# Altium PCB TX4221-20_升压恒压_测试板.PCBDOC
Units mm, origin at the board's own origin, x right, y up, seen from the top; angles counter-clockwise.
Board outline 40.25 x 32.29 mm, 2 copper layers (TopLayer, BottomLayer); 23 components, 11 nets, 61 pads, 124 vias.
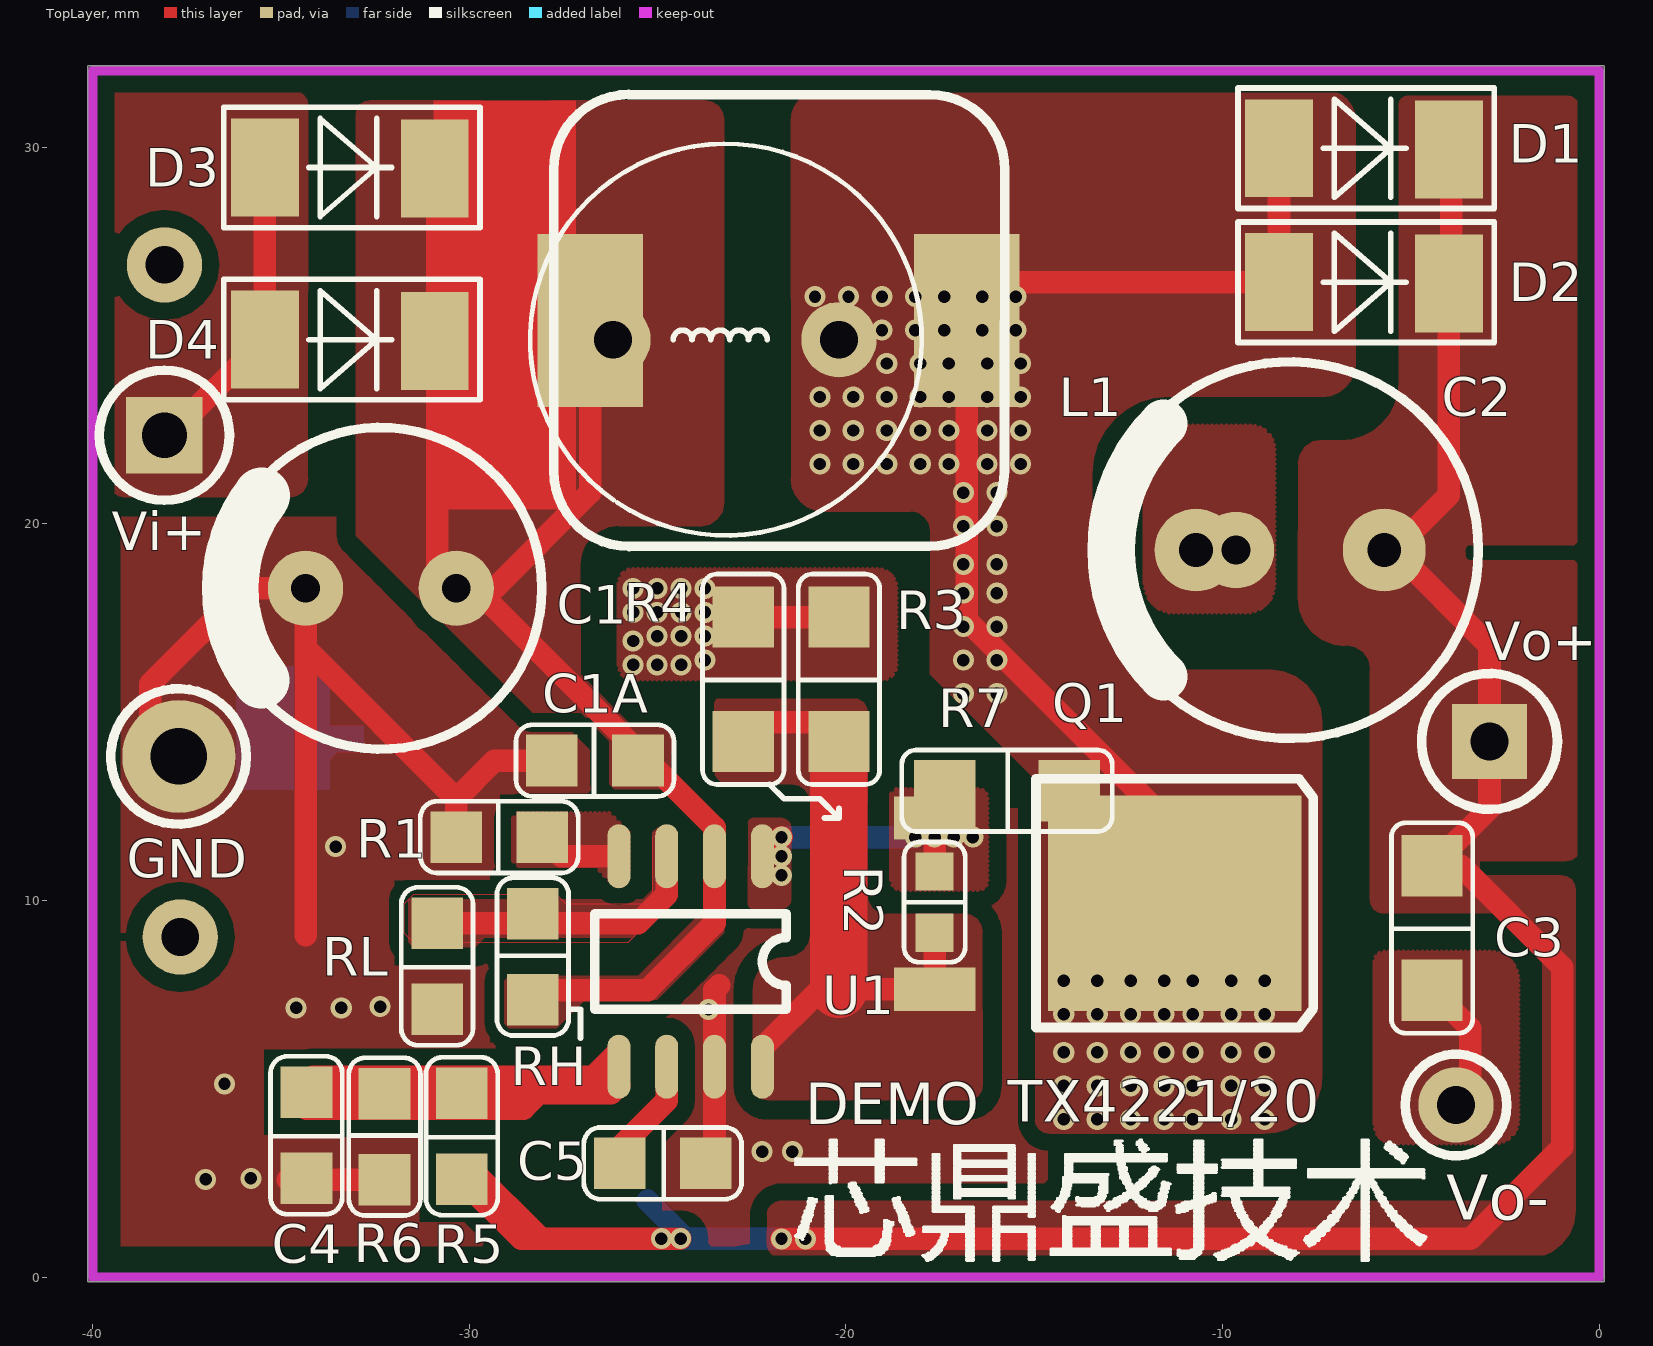
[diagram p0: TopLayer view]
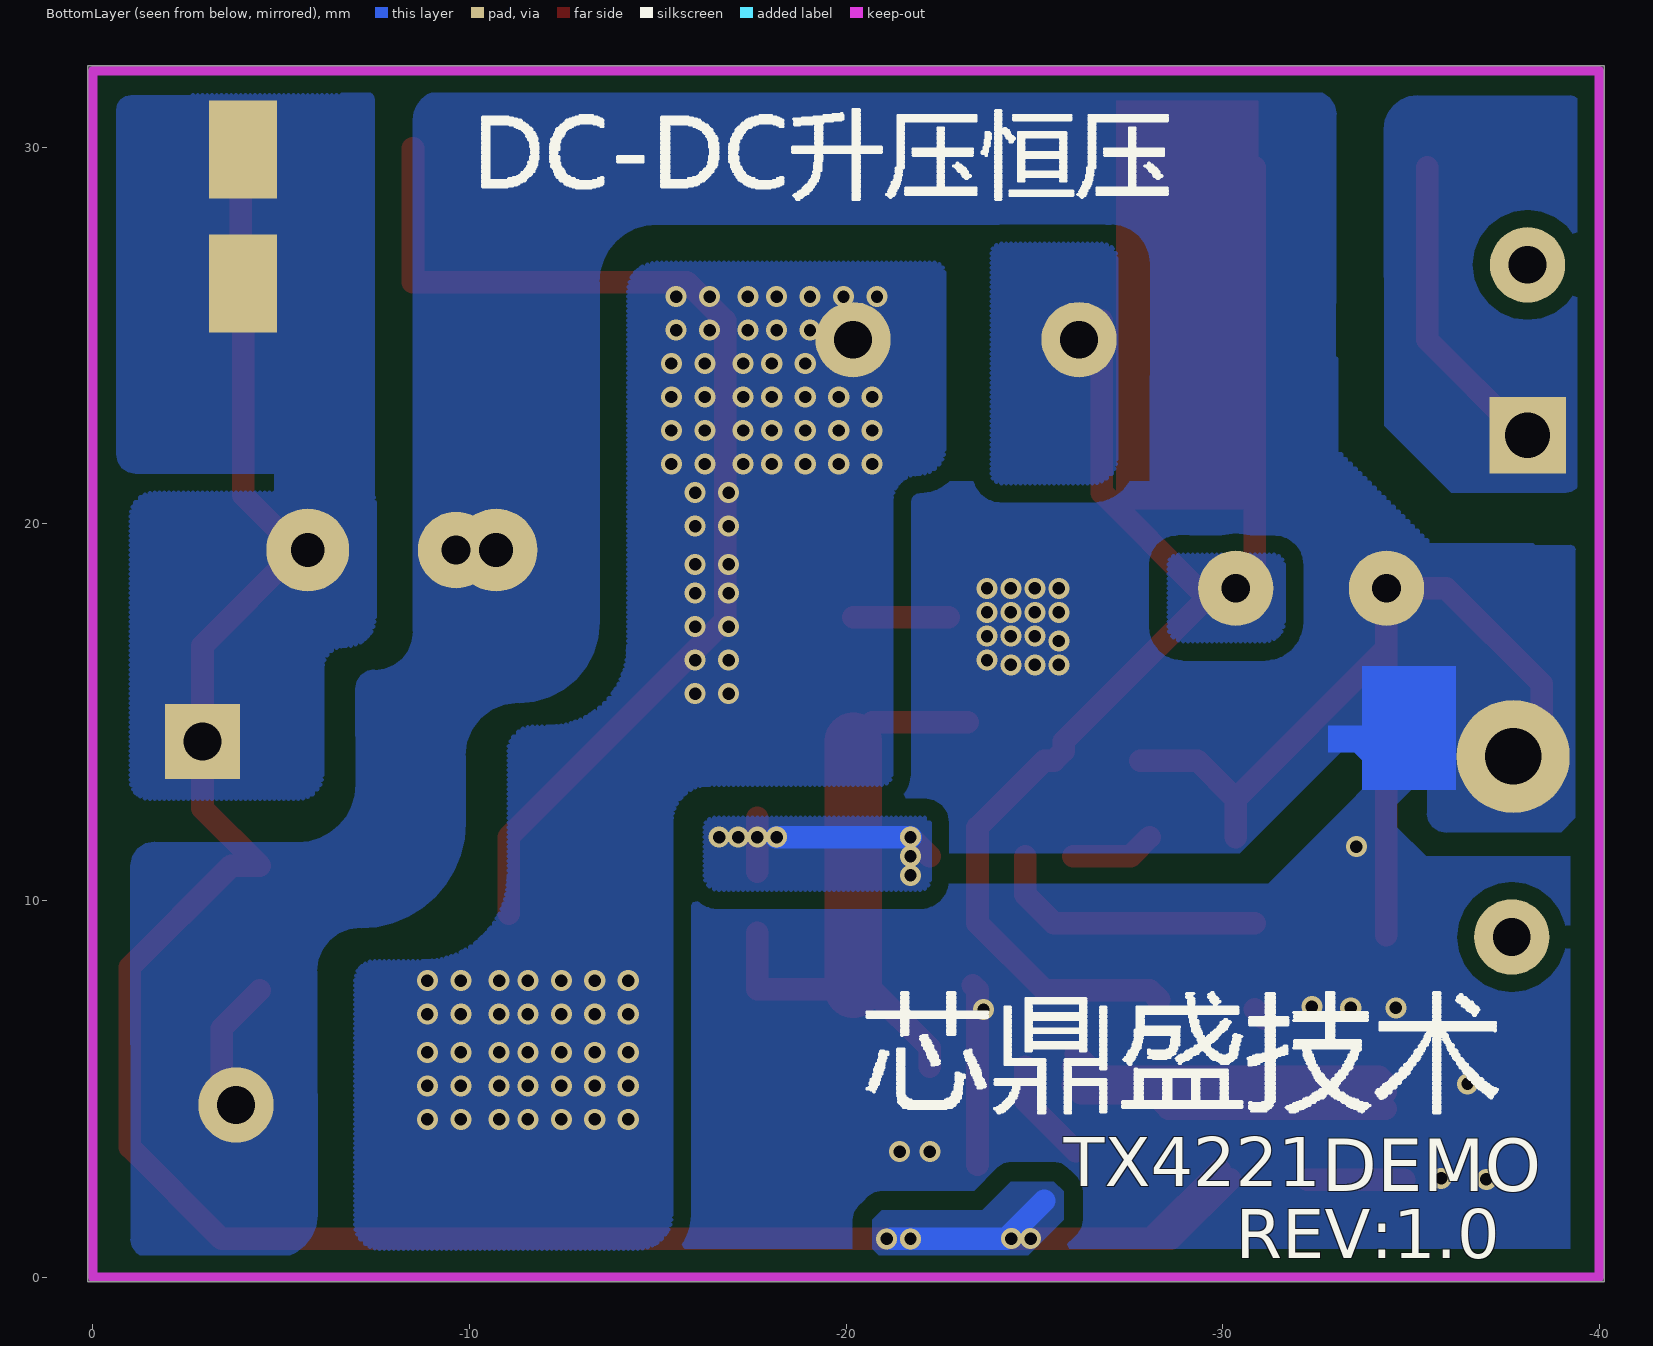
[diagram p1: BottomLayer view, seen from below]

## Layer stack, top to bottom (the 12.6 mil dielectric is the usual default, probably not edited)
TopLayer: signal copper 0.0356
Dielectric: dielectric 0.32, FR-4, Dk 4.8
BottomLayer: signal copper 0.0356

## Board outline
-40.127,-0.127 0.127,-0.127 0.127,32.159 -40.127,32.159

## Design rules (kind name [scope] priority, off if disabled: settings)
Clearance [All] p1: gap=0.45
ComponentClearance [All] p1 off: gap=0.254 collisioncheckmode=3 verticalgap=0.254 showdistances=FALSE
PolygonConnect [All] p1: connectstyle=Direct reliefconductorwidth=0.254 reliefentries=4 polygonreliefangle="90 Angle"
RoutingVias [All] p1: holewidth=0.711 width=1.27 viastyle="Through Hole" minholewidth=0.711 minwidth=1.27 maxholewidth=0.711 maxwidth=1.27
SilkscreenOverComponentPads [All] p1: minsilkscreentomaskgap=0.254
SolderMaskExpansion [All] p1: expansion=0.102
TestPointUsage [All] p1: valid=0 allowmultiple=FALSE
Testpoint [All] p1: side=15 testpointundercomponent=TRUE minsize=1.016 maxsize=2.54 preferedsize=1.524 minholesize=0.508 maxholesize=1.016 preferedholesize=0.813 testpointgrid=0.025 style=1023 order=0-112345678
Width [All] p1: maxlimit=1 minlimit=0.254 preferedwidth=0.6
22 further rules are at their usual default settings.

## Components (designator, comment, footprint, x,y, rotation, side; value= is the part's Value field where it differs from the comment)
C1 "" C8*12 -30.348,18.288 r90 top
C1A "" r0805 -27.808,13.716 r270 top
C2 "" C10*16 -5.71,19.304 r180 top
C3 "" r1206 -4.44,7.62 r180 top
C4 "" r0805 -34.325,2.625 r0 top
C5 "" r0805 -23.725,3.025 r90 top
D1 "" SMB#1 -8.504,26.416 r0 top
D2 "" SMB#1 -8.504,29.972 r0 top
D3 "" SMB#2 -35.428,29.464 r0 top
D4 "" SMB#2 -35.428,24.892 r0 top
L1 "" cdrh127 -26.792,25.4 r0 top
Q1 "" to252 -17.648,12.192 r270 top
R1 "" r0805 -30.348,11.684 r270 top
R2 "" r0603 -17.648,9.144 r90 top
R3 "" r1206 -20.188,14.224 r180 top
R4 "" r1206 -22.728,14.224 r180 top
R5 "" r0805 -30.2,2.6 r0 top
R6 "" r0805 -32.25,4.875 r180 top
R7 "" r1206 -14.075,12.916 r270 top
RH "" r0805 -28.316,9.652 r180 top
RL "" r0805 -30.856,7.112 r0 top
U1 "TX4221/20" SOP8 -22.22,11.176 r0 top
? "" L10*16 -20.188,24.892 r180 top

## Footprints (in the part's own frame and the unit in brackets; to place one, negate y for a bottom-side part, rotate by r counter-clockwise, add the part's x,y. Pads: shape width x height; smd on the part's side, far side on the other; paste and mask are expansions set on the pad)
C8*12 [mm]
  round 2 hole 0.762: 1(0,0) 2(0,4)
  silkscreen extent -4.27,-2.27 4.27,6.27
C10*16 [mm]
  round 2.2 hole 0.9: 1(0,0) 2(5,0)
  silkscreen extent -2.5,-5 7.5,5
cdrh127 [mm]
  rect 2.794x4.6 smd: 1(0,0) 2(10,0)
  silkscreen extent -0.97,-6 11.01,6
L10*16 [mm]
  round 2 hole 1: 1(0,0) 2(6,0)
  silkscreen extent -2.2,-5.2 8.2,5.2
r0603 [mil]
  rect 40x40 smd: 1(0,0) 2(64,0)
  silkscreen extent -31,-32 95,32
r0805 [mil]
  rect 54x54 smd: 1(0,0) 2(0,90)
  silkscreen extent -38,-38 38,128
r1206 [mil]
  rect 64x64 smd: 1(0,0) 2(0,-130)
  silkscreen extent -43,-175 43,45
SMB#1 [mm]
  rect 1.8x2.6 smd: 1(0,0)
  rect 1.8x2.6 all layers, no hole: 2(4.511,-0.031)
  silkscreen extent -1.09,-1.6 5.71,1.6
SMB#2 [mm]
  rect 1.8x2.6 smd: 1(0,0) 2(4.511,-0.031)
  silkscreen extent -1.09,-1.6 5.71,1.6
SOP8 [mil]
  oval 24x66.93 smd: 1(0,0) 2(-50,0) 3(-100,0) 4(-150,0) 5(-150,-220) 6(-100,-220) 7(-50,-220) 8(0,-220)
  round 27.56 on Top Overlay: ""(-22.13,-84.65)
  silkscreen extent -175,-160 25,-60
to252 [mil]
  rect 45x85 smd: 1(0,0) 3(179,0)
  rect 225x265 smd: 2(89,251)
  silkscreen extent -41,106 219,396

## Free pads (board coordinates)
  rect 2x2 hole 1: 1(-2.916,14.224)
  round 2 hole 1: 2(-3.805,4.572) 4(-38.095,26.875) 4(-37.675,9.032)
  rect 2.032x2.032 hole 1.2: 3(-38.095,22.352)
  round 3 hole 1.5: 4(-37.714,13.825)
  round 2.032 hole 0.762: 5(-9.647,19.304)

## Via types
v1: diameter 0.559, hole 0.33, TopLayer to BottomLayer, 124 vias

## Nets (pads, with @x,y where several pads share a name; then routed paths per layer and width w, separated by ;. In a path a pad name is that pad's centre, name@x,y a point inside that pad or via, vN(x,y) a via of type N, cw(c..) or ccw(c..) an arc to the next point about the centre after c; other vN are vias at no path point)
GND_0: C1.2 C1A.1 C2.2 C3.1 C4.1 C5.1 pad.2 pad.4@-37.714,13.825 pad.5 R1.1 R3.2 R4.2 R6.2 RL.1 U1.7 | length 39
  TopLayer w0.6: pad.4@-38.476,14.224 -38.476,15.748 -35.936,18.288 C1.2 -34.348,9.08 ; C4.1@-34.814,2.589 R6.2 ; -34.348,16.7 -30.348,12.7 ; RL.1@-31.11,6.858 RL.1 ; R1.1 -30.348,12.7 ; C1A.1 -29.332,13.716 -30.348,12.7 ; C5.1@-23.49,2.99 U1.7@-23.49,5.85 ; U1.7 -23.49,7.625 -23.368,7.747 ; R4.2 R3.2 ; C3.1 -3.424,6.604 pad.2@-3.424,5.08
  other v1: -37.001,2.6 -35.801,2.625 -22.225,3.332 -21.425,3.332 -36.5,5.132 -23.65,7.107 -34.601,7.15 -33.401,7.15 -32.367,7.182 -33.55,11.432 -25.649,16.256 -25.014,16.256 -24.379,16.256 -23.744,16.383 -25.649,16.891 -25.014,17.018 -24.379,17.018 -23.744,17.018 -25.649,17.653 -25.014,17.653 -24.379,17.653 -23.744,17.653 -25.649,18.288 -25.014,18.288 -24.379,18.288 -23.744,18.288
NetC1_1: ?.2 C1.1 C1A.2 D3.2 D4.2 L1.1 RH.2 U1.2 | length 38.4
  TopLayer w0.6: D3.2@-30.856,29.464 -30.856,18.796 C1.1 ; RH.2 -28.062,7.62 -25.268,7.62 -23.49,9.398 -23.49,11.938 -25.268,13.716 C1A.2 -25.776,13.97 -25.776,14.224 -29.84,18.288 C1.1 ; L1.1 -26.792,20.828 -29.332,18.288 C1.1
NetD3_1: D3.1 D4.1 pad.3 | length 8.7
  TopLayer w0.6: pad.3@-38.476,22.352 -37.968,22.352 D4.1 D3.1
NetL1_2: ?.1 D1.1 D2.1 L1.2 Q1.2 R7.1 | length 30.4
  TopLayer w0.6: Q1.2@-11.044,9.652 -11.044,11.684 -16.792,17.432 L1.2 -15.776,26.416 D1.1 D2.1
  other v1: -14.219,4.191 -13.33,4.191 -12.441,4.191 -11.552,4.191 -10.79,4.191 -9.774,4.191 -8.885,4.191 -14.219,5.08 -13.33,5.08 -12.441,5.08 -11.552,5.08 -10.79,5.08 -9.774,5.08 -8.885,5.08 -14.219,5.969 -13.33,5.969 -12.441,5.969 -11.552,5.969 -10.79,5.969 -9.774,5.969 -8.885,5.969 -14.219,6.985 -13.33,6.985 -12.441,6.985 -11.552,6.985 -10.79,6.985 -9.774,6.985 -8.885,6.985 -14.219,7.874 -13.33,7.874 -12.441,7.874 -11.552,7.874 -10.79,7.874 -9.774,7.874 -8.885,7.874 -16.886,15.494 -15.997,15.494 -16.886,16.383 -15.997,16.383 -16.886,17.272 -15.997,17.272 -16.886,18.161 -15.997,18.161 -16.886,18.923 -15.997,18.923 -16.886,19.939 -15.997,19.939 -16.886,20.828 -15.997,20.828 -20.696,21.59 -19.807,21.59 -18.918,21.59 -18.029,21.59 -17.267,21.59 -16.251,21.59 -15.362,21.59 -20.696,22.479 -19.807,22.479 -18.918,22.479 -18.029,22.479 -17.267,22.479 -16.251,22.479 -15.362,22.479 -20.696,23.368 -19.807,23.368 -18.918,23.368 -18.029,23.368 -17.267,23.368 -16.251,23.368 -15.362,23.368 -18.918,24.257 -18.029,24.257 -17.267,24.257 -16.251,24.257 -15.362,24.257 -19.045,25.146 -18.156,25.146 -17.394,25.146 -16.378,25.146 -15.489,25.146 -20.823,26.035 -19.934,26.035 -19.045,26.035 -18.156,26.035 -17.394,26.035 -16.378,26.035 -15.489,26.035
NetR1_2: R1.2 U1.4 | length 2.2
  TopLayer w0.6: R1.2 -27.554,11.176 U1.4
NetR5_1: C2.1 C3.2 D1.2 D2.2 pad.1 R5.1 | length 67
  TopLayer w0.6: R5.1 -28.625,1.025 v1@-24.4,1.025 ; R5.1@-29.925,2.85 -28.1,1.025 -27.6,1.025 ; v1(-21.712,1.016) -3.424,1.016 -0.988,3.452 -0.988,8.232 -3.678,10.922 C3.2 -2.916,12.446 -2.916,16.764 C2.1@-5.456,19.304 ; C2.1@-4.948,19.304 C2.1@-5.456,19.304 ; D2.2@-3.932,29.972 -3.932,26.446 D1.2 -3.993,20.767 C2.1@-5.456,19.304
  BottomLayer w0.6: -25.268,2.032 -24.252,1.016 v1@-21.204,1.016
  other v1: -24.9,1.025 -24.392,1.025 -21.077,1.016
NetRH_1: RH.1 RL.2 U1.3 | length 7.4
  TopLayer w0.6: RL.2 -28.57,9.398 -25.522,9.398 -24.76,10.16 U1.3
NetU1_1: Q1.1 R2.2 R7.2 U1.1 | length 5.7
  TopLayer w0.6: U1.1 v1(-21.712,11.684) ; R2.2 Q1.1
  BottomLayer w0.6: v1(-21.712,11.684) v1(-18.156,11.684)
  other v1: -21.712,10.668 -21.712,11.176 -17.648,11.684 -17.14,11.684 -16.632,11.684
NetU1_5: C4.2 R5.2 R6.1 U1.5 | length 24.3
  TopLayer w0.6: C4.2@-34.325,4.475 -28.561,4.475 -28.15,4.886 ; C4.2 -34.3,4.886 -26.732,4.886 ; C4.2@-34.325,5.15 -34.15,5.325 -26.7,5.325 U1.5@-26.1,5.925 ; U1.5 -26.732,4.886 ; U1.5@-26.025,5.1 -26.239,4.886 -26.732,4.886
NetU1_6: C5.2 U1.6 | length 2.8
  TopLayer w0.6: C5.2@-26.1,3.35 -24.76,4.69 U1.6
NetU1_8: Q1.3 R2.1 R3.1 R4.1 U1.8 | length 16.3
  TopLayer w0.6: R4.1@-23.236,14.732 R3.1@-20.696,14.732 ; U1.8 -22.22,6.096 -20.671,7.645 Q1.3 R2.1
  TopLayer w1.524: -20.188,7.645 R3.1
pads on no net: U1.

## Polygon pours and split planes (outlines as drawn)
GND_0 on TopLayer "TopLayer-GND_0 3" (solid, remove dead copper, pour order 1015): -39.25,0.825 -14.65,0.825 -14.65,12.45 -23.617,12.45 -31.36,20.193 -39.25,20.193
GND_0 on TopLayer "TopLayer-GND_0 2" (hatched 90Degree grid 0.127 track 0.127, remove dead copper, pour order 1014): -25.268,18.796 -19.172,18.796 cw(c-19.172,18.288) -18.664,18.288 -18.664,16.256 cw(c-19.045,16.256) -19.045,15.875 -25.649,15.875 cw(c-25.649,16.256) -26.03,16.256 -26.03,18.415 cw(c-25.649,18.415) -25.649,18.796
NetL1_2 on TopLayer "TopLayer-NetL1_2" (solid, remove dead copper, pour order 1013): -14.981,7.112 -14.981,13.208 -17.775,16.002 -17.775,19.812 ccw(c-18.283,19.812) -18.283,20.32 -20.569,20.32 cw(c-20.569,21.209) -21.458,21.209 -21.458,30.734 cw(c-20.696,30.734) -20.696,31.496 -7.234,31.496 cw(c-7.234,30.734) -6.472,30.734 -6.472,24.257 cw(c-7.361,24.257) -7.361,23.368 -11.425,23.368 ccw(c-11.425,21.336) -13.457,21.336 -13.457,18.542 ccw(c-11.044,18.542) -11.044,16.129 -8.758,16.129 cw(c-8.758,14.732) -7.361,14.732 -7.361,5.334 cw(c-8.885,5.334) -8.885,3.81 -14.6,3.81 cw(c-14.6,4.191) -14.981,4.191
NetU1_8 on TopLayer "TopLayer-NetU1_8" (solid, remove dead copper, pour order 1012): -23.363,15.367 -19.807,15.367 cw(c-19.807,14.986) -19.426,14.986 -19.426,10.16 ccw(c-18.918,10.16) -18.918,9.652 -16.886,9.652 cw(c-16.886,9.144) -16.378,9.144 -16.378,5.08 cw(c-16.759,5.08) -16.759,4.699 -22.093,4.699 cw(c-22.093,5.08) -22.474,5.08 -22.474,7.62 cw(c-21.585,7.62) -21.585,8.509 ccw(c-21.585,9.144) -20.95,9.144 -20.95,12.573 ccw(c-21.458,12.573) -21.458,13.081 -23.109,13.081 cw(c-23.109,13.462) -23.49,13.462 -23.49,15.24 cw(c-23.363,15.24)
NetU1_1 on TopLayer "TopLayer-NetU1_1 1" (solid, remove dead copper, pour order 1011): -22.601,11.938 -22.601,9.906 ccw(c-22.474,9.906) -22.474,9.779 -21.712,9.779 ccw(c-21.712,10.033) -21.458,10.033 -21.458,11.938 ccw(c-21.712,11.938) -21.712,12.192 -22.474,12.192 ccw(c-22.474,12.065) -22.601,12.065
NetU1_1 on TopLayer "TopLayer-NetU1_1" (hatched 90Degree grid 0.127 track 0.127, remove dead copper, pour order 1010): -18.791,12.7 -18.791,10.541 ccw(c-18.537,10.541) -18.537,10.287 -16.505,10.287 ccw(c-16.505,10.541) -16.251,10.541 -16.251,12.7 ccw(c-16.505,12.7) -16.505,12.954 -18.664,12.954 ccw(c-18.664,12.827) -18.791,12.827
NetD3_1 on TopLayer "TopLayer-NetD3_1" (solid, remove dead copper, pour order 1009): -39.619,31.115 -39.619,21.209 ccw(c-39.111,21.209) -39.111,20.701 -34.793,20.701 ccw(c-34.793,21.209) -34.285,21.209 -34.285,31.115 ccw(c-34.666,31.115) -34.666,31.496 -39.492,31.496 ccw(c-39.492,31.369) -39.619,31.369
NetC1_1 on TopLayer "TopLayer-NetC1_1" (solid, remove dead copper, pour order 1008): -33.015,30.734 -33.015,20.574 -32.761,20.32 -33.015,20.574 -33.015,19.685 -28.316,14.986 -27.046,14.986 -26.284,14.224 -26.284,13.081 -26.157,12.954 -24.887,12.954 -23.744,11.811 -23.744,9.779 -25.522,8.001 -28.951,8.001 -29.078,7.874 -29.078,6.731 -28.951,6.604 -27.681,6.604 -26.919,7.366 -25.014,7.366 -23.236,9.144 -23.236,12.065 -24.633,13.462 -24.633,14.351 ccw(c-24.887,14.351) -24.887,14.605 -25.649,14.605 -27.046,16.002 -27.046,18.923 cw(c-26.03,18.923) -26.03,19.939 -23.871,19.939 ccw(c-23.871,20.574) -23.236,20.574 -23.236,30.734 ccw(c-23.744,30.734) -23.744,31.242 -27.808,31.242 ccw(c-27.808,30.353) -28.697,30.353 -28.697,21.209 cw(c-28.951,21.209) -28.951,20.955 cw(c-28.951,21.209) -29.205,21.209 -29.205,30.734 ccw(c-29.713,30.734) -29.713,31.242 -32.634,31.242 ccw(c-32.634,30.861) -33.015,30.861
NetR5_1 on TopLayer "TopLayer-NetR5_1 1" (solid, remove dead copper, pour order 1007): -5.329,31.115 -5.329,23.749 cw(c-6.853,23.749) -6.853,22.225 -7.361,22.225 ccw(c-7.361,21.59) -7.996,21.59 -7.996,18.034 ccw(c-6.726,18.034) -6.726,16.764 cw(c-6.726,16.129) -6.091,16.129 -6.091,10.033 ccw(c-5.71,10.033) -5.71,9.652 -2.408,9.652 cw(c-2.408,8.763) -1.519,8.763 -1.519,3.175 cw(c-2.662,3.175) -2.662,2.032 -21.712,2.032 ccw(c-21.712,1.651) -22.093,1.651 -22.093,0.889 ccw(c-21.712,0.889) -21.712,0.508 -1.9,0.508 ccw(c-1.9,1.778) -0.63,1.778 -0.63,10.287 ccw(c-1.011,10.287) -1.011,10.668 -3.17,10.668 -3.17,11.049 -0.884,11.049 ccw(c-0.884,11.43) -0.503,11.43 -0.503,18.923 ccw(c-0.63,18.923) -0.63,19.05 -3.424,19.05 cw(c-3.424,19.177) -3.551,19.177 -3.551,19.304 cw(c-3.424,19.304) -3.424,19.431 -0.63,19.431 ccw(c-0.63,19.558) -0.503,19.558 -0.503,30.988 ccw(c-0.884,30.988) -0.884,31.369 -5.075,31.369 ccw(c-5.075,31.115)
GND_0 on TopLayer "TopLayer-GND_0 1" (hatched 90Degree grid 0.127 track 0.127, remove dead copper, pour order 1006): -5.964,8.382 -5.964,4.064 ccw(c-5.456,4.064) -5.456,3.556 -2.789,3.556 ccw(c-2.789,4.191) -2.154,4.191 -2.154,7.874 ccw(c-2.916,7.874) -2.916,8.636 -5.71,8.636 ccw(c-5.71,8.382)
NetR5_1 on TopLayer "TopLayer-NetR5_1" (hatched 90Degree grid 0.127 track 0.127, remove dead copper, pour order 1005): -26.03,3.81
NetU1_5 on TopLayer "TopLayer-NetU1_5" (hatched 90Degree grid 0.127 track 0.127, remove dead copper, pour order 1004): -34.539,3.937
GND_0 on TopLayer "TopLayer-GND_0" (hatched 90Degree grid 0.127 track 0.127, remove dead copper, pour order 1003): -12.06,21.463 -12.06,18.415 ccw(c-11.298,18.415) -11.298,17.653 -9.393,17.653 ccw(c-9.393,18.415) -8.631,18.415 -8.631,21.971 ccw(c-9.266,21.971) -9.266,22.606 -11.679,22.606 ccw(c-11.679,22.225) -12.06,22.225
NetR1_2 on TopLayer "TopLayer-NetR1_2 1" (solid, remove dead copper, pour order 1002): -25.141,11.684 -25.141,10.16 -25.395,9.906 -27.427,9.906 -27.681,10.16 -31.491,10.16 -31.745,9.906 -31.745,9.144 -31.491,8.89 -25.776,8.89 -24.506,10.16 -24.506,11.684 -24.633,11.811 -25.014,11.811
NetRH_1 on TopLayer "TopLayer-NetRH_1" (solid, remove dead copper, pour order 1001): -31.618,10.033 -25.395,10.033 -25.141,10.287 -25.141,11.811 -25.014,11.938 -24.633,11.938 -24.506,11.811 -24.506,10.16 -25.649,9.017 -29.586,9.017 -29.84,8.763 -31.491,8.763 -31.618,8.89
NetR1_2 on TopLayer "TopLayer-NetR1_2" (hatched 90Degree grid 0.127 track 0.127, remove dead copper, pour order 1000): -28.697,12.319 -26.284,12.319 -26.03,12.065 -25.776,11.811 -25.776,10.795 -26.03,10.541 -26.284,10.541 -26.665,10.922 -28.697,10.922 -28.824,11.049 -28.824,12.192
GND_0 on BottomLayer "BottomLayer-GND_0 5" (solid, remove dead copper, pour order 1030): -35.875,15.113 -31.212,10.45 -14.219,10.45 -14.219,0.762 -39.225,0.762 -39.225,11.175 -35.4,11.175 -34.625,11.95 -34.625,12.55 -36.045,13.97 -36.045,15.113
GND_0 on BottomLayer "BottomLayer-GND_0 4" (solid, remove dead copper, pour order 1029): -35.174,15.975 -30.456,11.257 -18.672,11.257 -18.672,21.132 -32.134,21.132 -35.182,18.084 -35.182,16.057
NetR5_1 on BottomLayer "BottomLayer-NetR5_1 3" (solid, remove dead copper, pour order 1028): -25.395,2.54 -24.379,2.54 -23.617,1.778 -20.95,1.778 -20.696,1.524 -20.696,0.762 -20.95,0.508 -24.76,0.508 -25.776,1.524 -25.776,2.286 -25.522,2.54
NetU1_1 on BottomLayer "BottomLayer-NetU1_1" (hatched 90Degree grid 0.127 track 0.127, remove dead copper, pour order 1027): -21.839,12.192 -16.505,12.192 cw(c-16.505,11.938) -16.251,11.938 -16.251,10.668 cw(c-16.632,10.668) -16.632,10.287 -21.966,10.287 cw(c-21.966,10.541) -22.22,10.541 -22.22,12.065 cw(c-22.093,12.065) -22.093,12.192
NetR5_1 on BottomLayer "BottomLayer-NetR5_1 2" (hatched 90Degree grid 0.127 track 0.127, remove dead copper, pour order 1026): -7.488,20.32 -7.488,17.526 ccw(c-6.726,17.526) -6.726,16.764 cw(c-6.726,16.129) -6.091,16.129 -6.091,13.335 ccw(c-5.456,13.335) -5.456,12.7 -1.519,12.7 ccw(c-1.519,13.208) -1.011,13.208 -1.011,20.193 ccw(c-1.646,20.193) -1.646,20.828 -7.234,20.828 ccw(c-7.234,20.574) -7.488,20.574
GND_0 on BottomLayer "BottomLayer-GND_0 3" (solid, remove dead copper, pour order 1025): -39.365,19.334 -39.365,12.192 -38.984,11.811 -35.936,11.811 ccw(c-35.936,12.319) -35.428,12.319 -35.428,16.764 cw(c-35.047,16.764) -35.047,17.145 ccw(c-35.047,17.526) -34.666,17.526 -34.666,19.304 ccw(c-34.793,19.304) -34.793,19.431 -39.238,19.431 ccw(c-39.238,19.304) -39.365,19.304
GND_0 on BottomLayer "BottomLayer-GND_0 2" (solid, remove dead copper, pour order 1024): -1.011,1.397 -1.011,10.922 ccw(c-1.646,10.922) -1.646,11.557 -5.456,11.557 cw(c-5.456,13.081) -6.98,13.081 -6.98,15.621 ccw(c-7.488,15.621) -7.488,16.129 cw(c-7.488,17.145) -8.504,17.145 -8.504,30.226 cw(c-8.504,31.369) -9.647,31.369 ccw(c-8.504,31.369) -8.504,30.226 -8.504,30.734 ccw(c-9.266,30.734) -9.266,31.496 -32.38,31.496 ccw(c-32.38,30.861) -33.015,30.861 -33.015,20.828 cw(c-34.412,20.828) -34.412,19.431 -35.047,19.431 ccw(c-35.047,17.272) -37.206,17.272 -37.206,16.51 ccw(c-36.825,16.51) -36.825,16.129 -35.428,16.129 ccw(c-35.047,16.129) -35.047,15.748 -33.777,15.748 ccw(c-33.777,16.637) -32.888,16.637 cw(c-32.634,16.637) -32.634,16.891 ccw(c-32.634,17.145) -32.38,17.145 -32.38,18.542 cw(c-31.237,18.542) -31.237,19.685 -29.332,19.685 ccw(c-29.332,20.955) -28.062,20.955 -28.062,26.924 cw(c-27.046,26.924) -27.046,27.94 -14.981,27.94 cw(c-14.981,26.416) -13.457,26.416 -13.457,17.399 cw(c-13.457,14.732) -10.79,14.732 ccw(c-13.457,14.732) -13.457,17.399 ccw(c-11.298,17.399) -11.298,15.24 cw(c-11.298,13.843) -9.901,13.843 -9.901,12.065 ccw(c-7.107,12.065) -7.107,9.271 cw(c-7.107,8.128) -5.964,8.128 -5.964,1.651 ccw(c-4.821,1.651) -4.821,0.508 -1.519,0.508 ccw(c-1.519,1.016) -1.011,1.016
NetR5_1 on BottomLayer "BottomLayer-NetR5_1 1" (solid, remove dead copper, pour order 1023): -6.853,22.733 -6.853,30.861 cw(c-6.345,30.861) -6.345,31.369 -1.011,31.369 cw(c-1.011,30.988) -0.63,30.988 -0.63,21.844 cw(c-1.138,21.844) -1.138,21.336 -4.821,21.336 -4.821,20.701 -7.488,20.701 -7.488,31.242 cw(c-7.234,31.242) -7.234,31.496 -3.297,31.496 -3.297,22.479 -6.853,22.479
NetR5_1 on BottomLayer "BottomLayer-NetR5_1" (hatched 90Degree grid 0.127 track 0.127, remove dead copper, pour order 1022): -6.98,22.098 -6.98,30.988 -6.599,31.369 -2.535,31.369 -2.535,21.971 -6.98,21.971
NetC1_1 on BottomLayer "BottomLayer-NetC1_1 1" (hatched 90Degree grid 0.127 track 0.127, remove dead copper, pour order 1021): -31.237,19.177 -28.824,19.177 cw(c-28.824,18.923) -28.57,18.923 -28.57,17.272 cw(c-28.951,17.272) -28.951,16.891 -31.11,16.891 cw(c-31.11,17.399) -31.618,17.399 -31.618,18.923 cw(c-31.364,18.923) -31.364,19.177
GND_0 on BottomLayer "BottomLayer-GND_0 1" (hatched 90Degree grid 0.127 track 0.127, remove dead copper, pour order 1020): -23.363,13.081
NetC1_1 on BottomLayer "BottomLayer-NetC1_1" (hatched 90Degree grid 0.127 track 0.127, remove dead copper, pour order 1019): -27.173,26.797 -27.173,21.717 ccw(c-26.538,21.717) -26.538,21.082 -24.125,21.082 ccw(c-24.125,21.336) -23.871,21.336 -23.871,27.178 ccw(c-24.125,27.178) -24.125,27.432 -26.792,27.432 ccw(c-26.792,27.051) -27.173,27.051
NetL1_2 on BottomLayer "BottomLayer-NetL1_2" (hatched 90Degree grid 0.127 track 0.127, remove dead copper, pour order 1018): -22.601,26.543 -22.601,21.971 ccw(c-21.966,21.971) -21.966,21.336 cw(c-21.966,20.574) -21.204,20.574 -21.204,13.335 ccw(c-20.95,13.335) -20.95,13.081 -16.378,13.081 cw(c-16.378,12.065) -15.362,12.065 -15.362,1.651 ccw(c-14.473,1.651) -14.473,0.762 -7.615,0.762 ccw(c-7.615,1.397) -6.98,1.397 -6.98,7.874 ccw(c-7.488,7.874) -7.488,8.382 -8.758,8.382 cw(c-8.758,10.668) -11.044,10.668 -11.044,13.97 ccw(c-11.679,13.97) -11.679,14.605 -12.06,14.605 cw(c-12.06,16.764) -14.219,16.764 -14.219,26.162 ccw(c-14.981,26.162) -14.981,26.924 -22.347,26.924 ccw(c-22.347,26.67) -22.601,26.67
GND_0 on BottomLayer "BottomLayer-GND_0" (hatched 90Degree grid 0.127 track 0.127, remove dead copper, pour order 1017): -33.015,24.384 -33.015,21.971 -35.555,19.431 -38.222,19.431 -38.222,16.383 -32.888,16.383 -32.888,19.207 -31.237,20.858 -31.237,24.384
NetD3_1 on BottomLayer "BottomLayer-NetD3_1" (solid, remove dead copper, pour order 1016): -39.111,20.828 -36.063,20.828 -34.285,22.606 -34.285,30.48 ccw(c-35.174,30.48) -35.174,31.369 -39.238,31.369 ccw(c-39.238,31.115) -39.492,31.115 -39.492,21.209 ccw(c-39.111,21.209)
NetR5_1 on BottomSolder (hatched 90Degree grid 0.127 track 0.127, remove dead copper): -6.853,31.369 -1.392,31.369 cw(c-1.392,30.861) -0.884,30.861 -0.884,21.717 cw(c-1.138,21.717) -1.138,21.463 -6.218,21.463 cw(c-6.218,22.225) -6.98,22.225 -6.98,31.242 cw(c-6.853,31.242)
GND_0 on BottomSolder (hatched 90Degree grid 0.127 track 0.127, remove dead copper): -32.38,17.272 -32.38,18.796 cw(c-31.364,18.796) -31.364,19.812 -30.602,19.812 ccw(c-30.602,20.066) -30.348,20.066 -30.348,20.574 ccw(c-30.729,20.574) -30.729,20.955 -33.015,20.955 -33.015,20.447 cw(c-34.158,20.447) -34.158,19.304 -35.428,19.304 ccw(c-35.428,18.923) -35.809,18.923 -35.809,16.891 ccw(c-35.555,16.891) -35.555,16.637 -32.634,16.637 ccw(c-32.634,16.891) -32.38,16.891
NetL1_2 on BottomSolder (hatched 90Degree grid 0.127 track 0.127, remove dead copper): -7.615,2.159 -7.615,7.62 ccw(c-8.25,7.62) -8.25,8.255 -9.647,8.255 cw(c-9.647,9.906) -11.298,9.906 -11.298,13.462 ccw(c-12.314,13.462) -12.314,14.478 -12.822,14.478 cw(c-12.822,16.129) -14.473,16.129 -14.473,21.336 ccw(c-15.489,21.336) -15.489,22.352 -19.807,22.352 ccw(c-19.807,21.336) -20.823,21.336 -20.823,13.97 ccw(c-20.188,13.97) -20.188,13.335 -15.87,13.335 cw(c-15.87,12.446) -14.981,12.446 -14.981,1.651 ccw(c-14.346,1.651) -14.346,1.016 -7.996,1.016 ccw(c-7.996,1.397) -7.615,1.397
NetD3_1 on BottomSolder (hatched 90Degree grid 0.127 track 0.127, remove dead copper): -36.19,21.209 -34.412,22.987 -34.412,30.353 ccw(c-35.301,30.353) -35.301,31.242 -38.984,31.242 ccw(c-38.984,30.77) -39.455,30.77 -39.455,21.336 ccw(c-39.074,21.336) -39.074,20.955 -36.444,20.955

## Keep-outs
KeepOutLayer:
  lines w0.254: -40,0 0,0 0,32.032 -40,32.032 -40,0

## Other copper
TopLayer:
  region net NetC1_1: -27.173,20.375 -27.173,31.242 -30.95,31.242 -30.95,20.375
BottomLayer:
  region net GND_0: -34.301,13.125 -33.126,14.3 -33.401,14.575 -34.576,13.4
  rectangle net GND_0: -34.925,13.925 -32.801,14.65
  rectangle net GND_0: -36.19,12.939 -33.701,16.225

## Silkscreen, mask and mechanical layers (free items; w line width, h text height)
TopOverlay:
  drawing of 1301 lines, arcs and shapes, not listed
  text "Vi+" at -39.492,19.304 h1.02
  text "Vo+" at -3.043,16.383 h1.02
  text "GND" at -39.101,10.6 h1.02
  text "DEMO" at -21.077,4.064 h1.1
  text "Vo-" at -4.059,1.524 h1.2
BottomOverlay:
  drawing of 2254 lines, arcs and shapes, not listed
  text "TX4221" at -25.776,2.413 h1.3
  text "DEMO" at -32.634,2.286 h1.4
  text "REV:1.0" at -30.348,0.508 h1.3
TopSolder:
  lines w0.8: -20.569,28.575 -9.774,28.575 ; -20.442,29.718 -9.774,29.718 ; -20.315,30.861 -9.52,30.861 ; -15.235,27.178 -9.647,27.178 ; -14.981,25.908 -9.52,25.908 ; -14.854,24.511 -9.52,24.511
  lines w2: -15.235,21.971 -15.235,17.018 -11.171,12.954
